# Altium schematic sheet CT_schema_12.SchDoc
size 390 x 385 mm
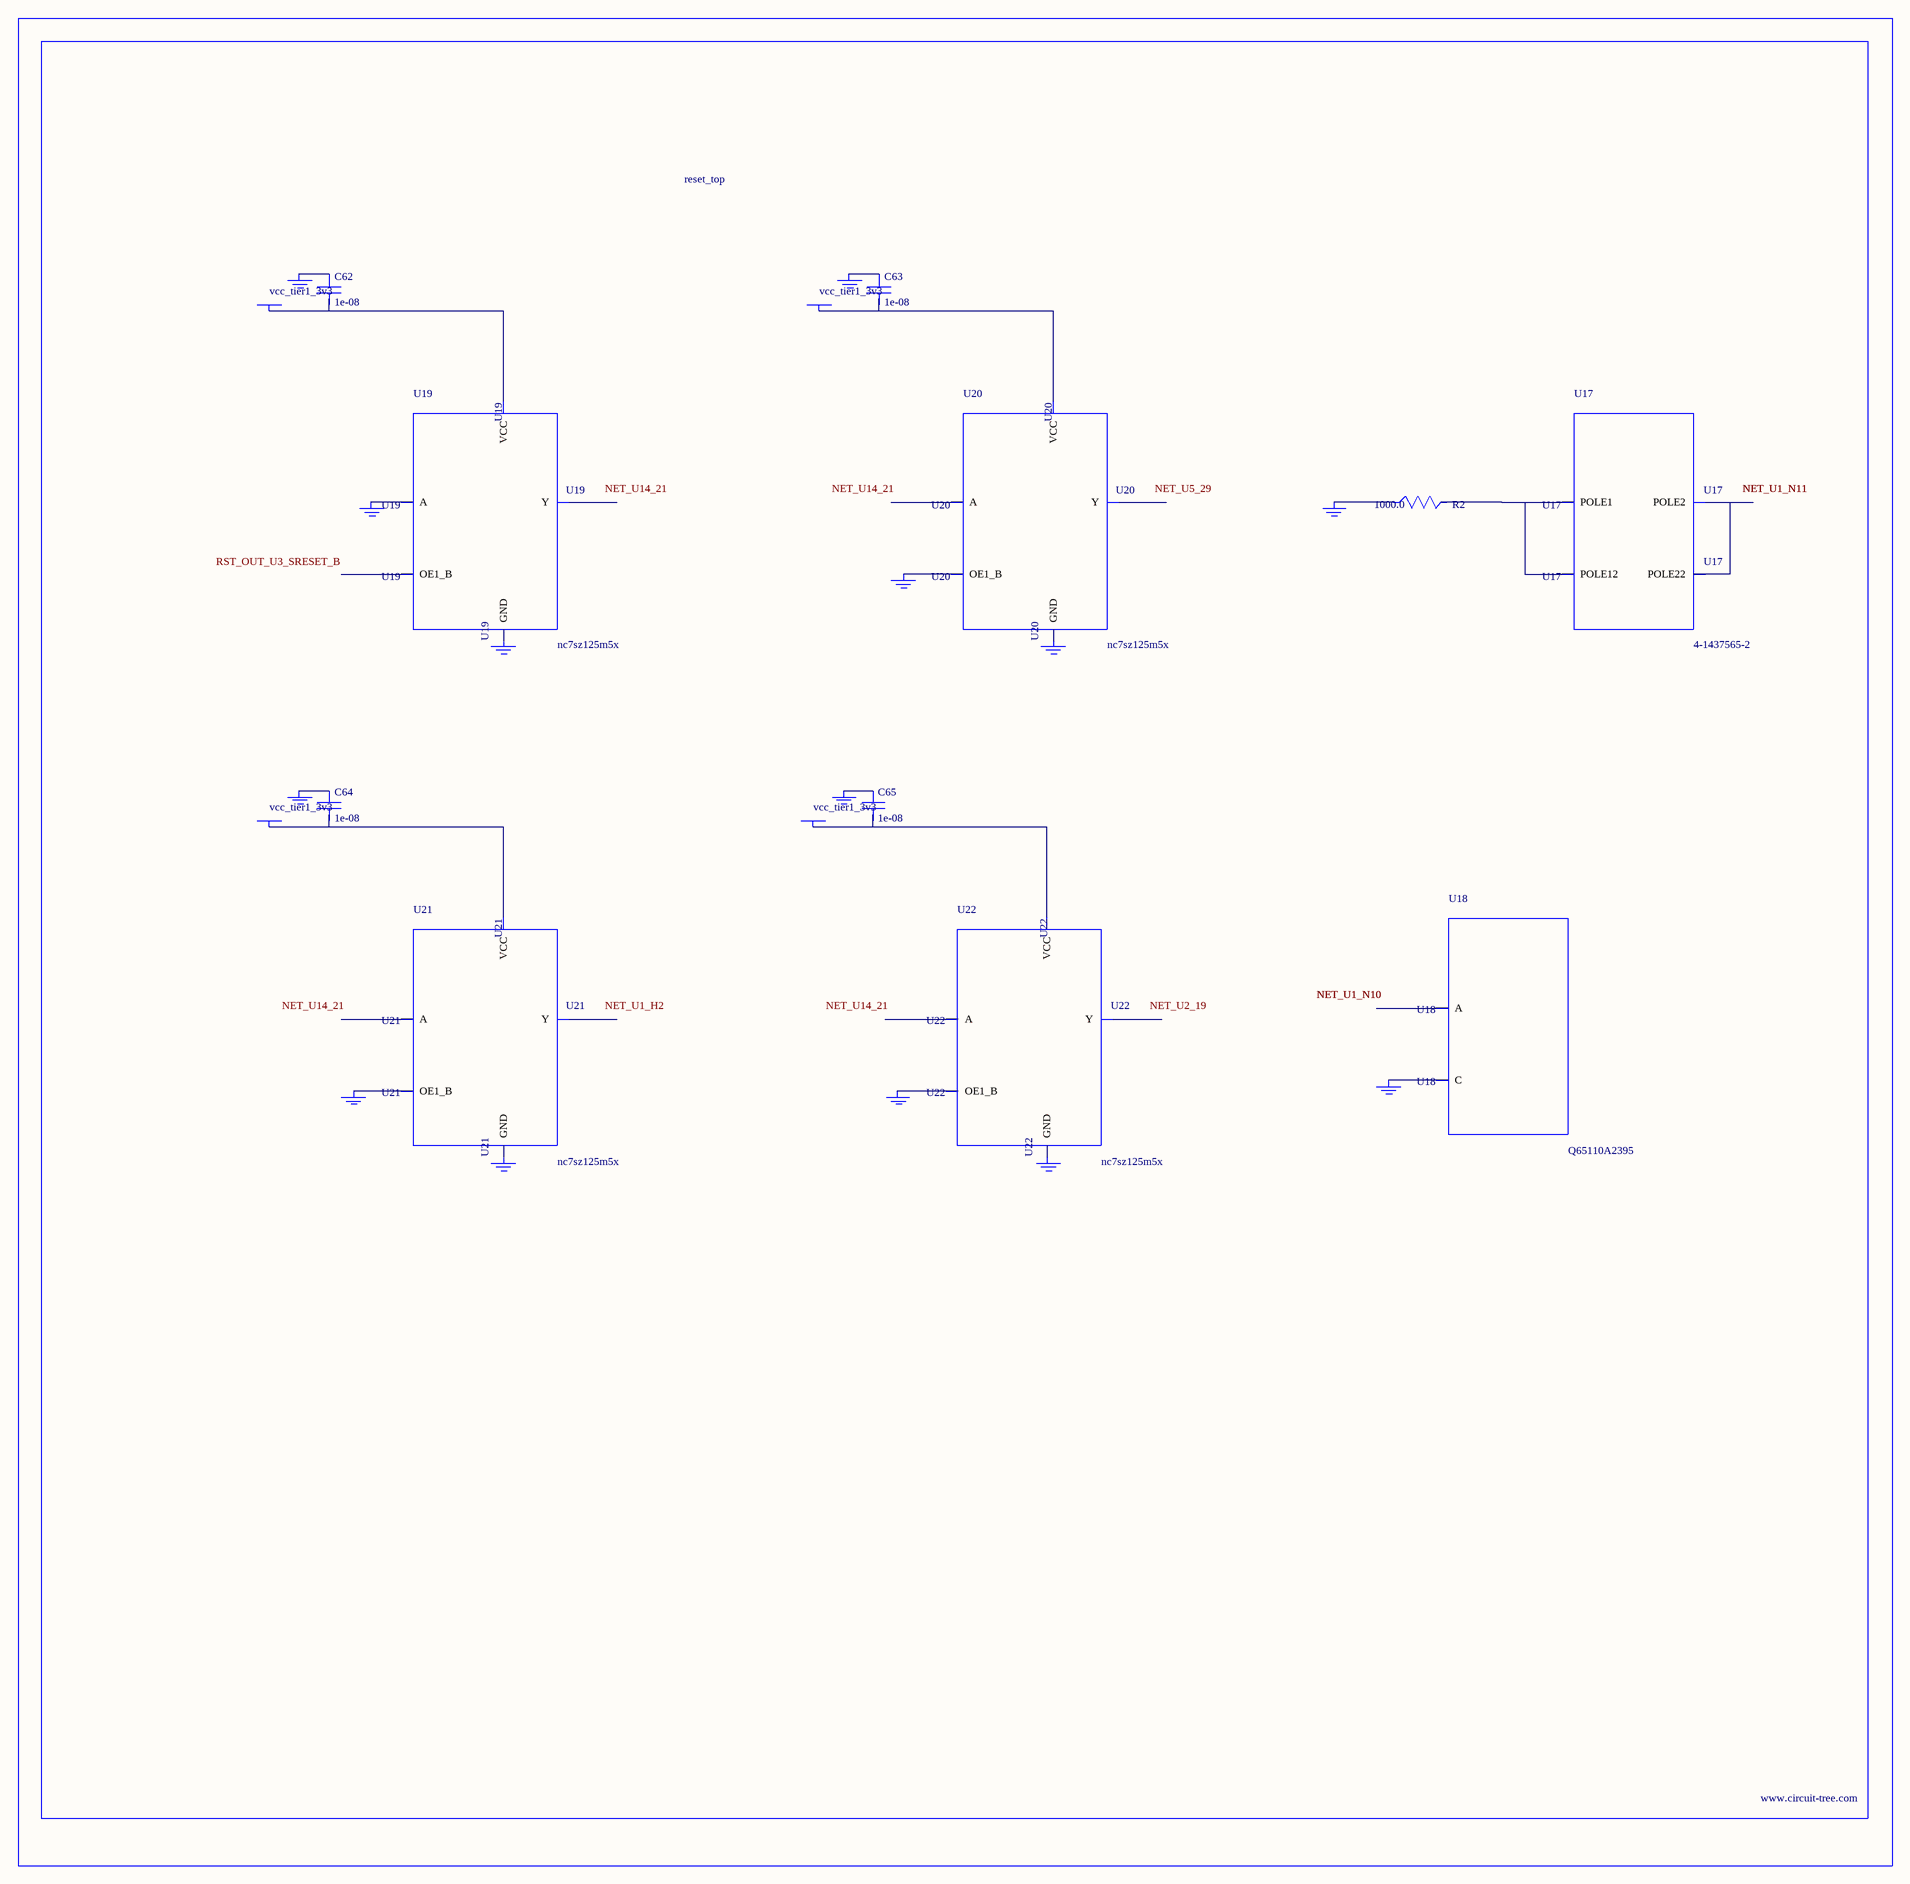
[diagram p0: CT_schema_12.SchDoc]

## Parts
BORDER11  (no value)
C62  1e-08  [C0402]
C63  1e-08  [C0402]
C64  1e-08  [C0402]
C65  1e-08  [C0402]
GND_INSTANCE_11_0  (no value)
GND_INSTANCE_11_1  (no value)
GND_INSTANCE_11_2  (no value)
GND_INSTANCE_11_3  (no value)
GND_INSTANCE_11_4  (no value)
GND_INSTANCE_11_5  (no value)
GND_INSTANCE_11_6  (no value)
GND_INSTANCE_11_7  (no value)
GND_INSTANCE_11_8  (no value)
GND_INSTANCE_11_9  (no value)
GND_INSTANCE_11_10  (no value)
GND_INSTANCE_11_11  (no value)
GND_INSTANCE_11_12  (no value)
GND_INSTANCE_11_13  (no value)
POWER_INSTANCE_11_0  vcc_tier1_3v3
POWER_INSTANCE_11_1  vcc_tier1_3v3
POWER_INSTANCE_11_2  vcc_tier1_3v3
POWER_INSTANCE_11_3  vcc_tier1_3v3
R2  1000.0  [R0603]
U17  4-1437565-2  [SW_4-1437565-2]
U18  Q65110A2395  [LGM67K-G1J2-24-Z]
U19  nc7sz125m5x  [NC7SZ125M5X]
U20  nc7sz125m5x  [NC7SZ125M5X]
U21  nc7sz125m5x  [NC7SZ125M5X]
U22  nc7sz125m5x  [NC7SZ125M5X]

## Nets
NetC62_1: C62.1 GND_INSTANCE_11_2.0(GND)
NetC62_2: C62.2 POWER_INSTANCE_11_0.0(PWR) U19.5(VCC)
NetC63_1: C63.1 GND_INSTANCE_11_5.0(GND)
NetC63_2: C63.2 POWER_INSTANCE_11_1.0(PWR) U20.5(VCC)
NetC64_1: C64.1 GND_INSTANCE_11_8.0(GND)
NetC64_2: C64.2 POWER_INSTANCE_11_2.0(PWR) U21.5(VCC)
NetC65_1: C65.1 GND_INSTANCE_11_11.0(GND)
NetC65_2: C65.2 POWER_INSTANCE_11_3.0(PWR) U22.5(VCC)
NetGND_INSTANCE_11_0_0: GND_INSTANCE_11_0.0(GND) R2.1
NetGND_INSTANCE_11_1_0: GND_INSTANCE_11_1.0(GND) U18.C
NetGND_INSTANCE_11_3_0: GND_INSTANCE_11_3.0(GND) U19.2(A)
NetGND_INSTANCE_11_4_0: GND_INSTANCE_11_4.0(GND) U19.3(GND)
NetGND_INSTANCE_11_6_0: GND_INSTANCE_11_6.0(GND) U20.1(OE1_B)
NetGND_INSTANCE_11_7_0: GND_INSTANCE_11_7.0(GND) U20.3(GND)
NetGND_INSTANCE_11_9_0: GND_INSTANCE_11_9.0(GND) U21.1(OE1_B)
NetGND_INSTANCE_11_10_0: GND_INSTANCE_11_10.0(GND) U21.3(GND)
NetGND_INSTANCE_11_12_0: GND_INSTANCE_11_12.0(GND) U22.1(OE1_B)
NetGND_INSTANCE_11_13_0: GND_INSTANCE_11_13.0(GND) U22.3(GND)
NetR2_2: R2.2 U17.1(POLE1) U17.2(POLE12)
NetU17_3: U17.3(POLE2) U17.4(POLE22)

Not connected (* = marked no-connect by the designer): U18 A; U19 1(OE1_B) 4(Y); U20 2(A) 4(Y); U21 2(A) 4(Y); U22 2(A) 4(Y)

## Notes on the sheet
- Labels drawn without touching a wire or pin: NET_U1_H2, NET_U2_19, NET_U5_29, NET_U14_21, RST_OUT_U3_SRESET_B

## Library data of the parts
BORDER11 = BORDER_PAGE11
C62-C65 = C0402C103K3RAC
GND_INSTANCE_11_0-GND_INSTANCE_11_13 = GND
POWER_INSTANCE_11_0-POWER_INSTANCE_11_3 = PWR
R2 = RC0603JR-071KL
